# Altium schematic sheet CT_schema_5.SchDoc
size 577 x 363 mm
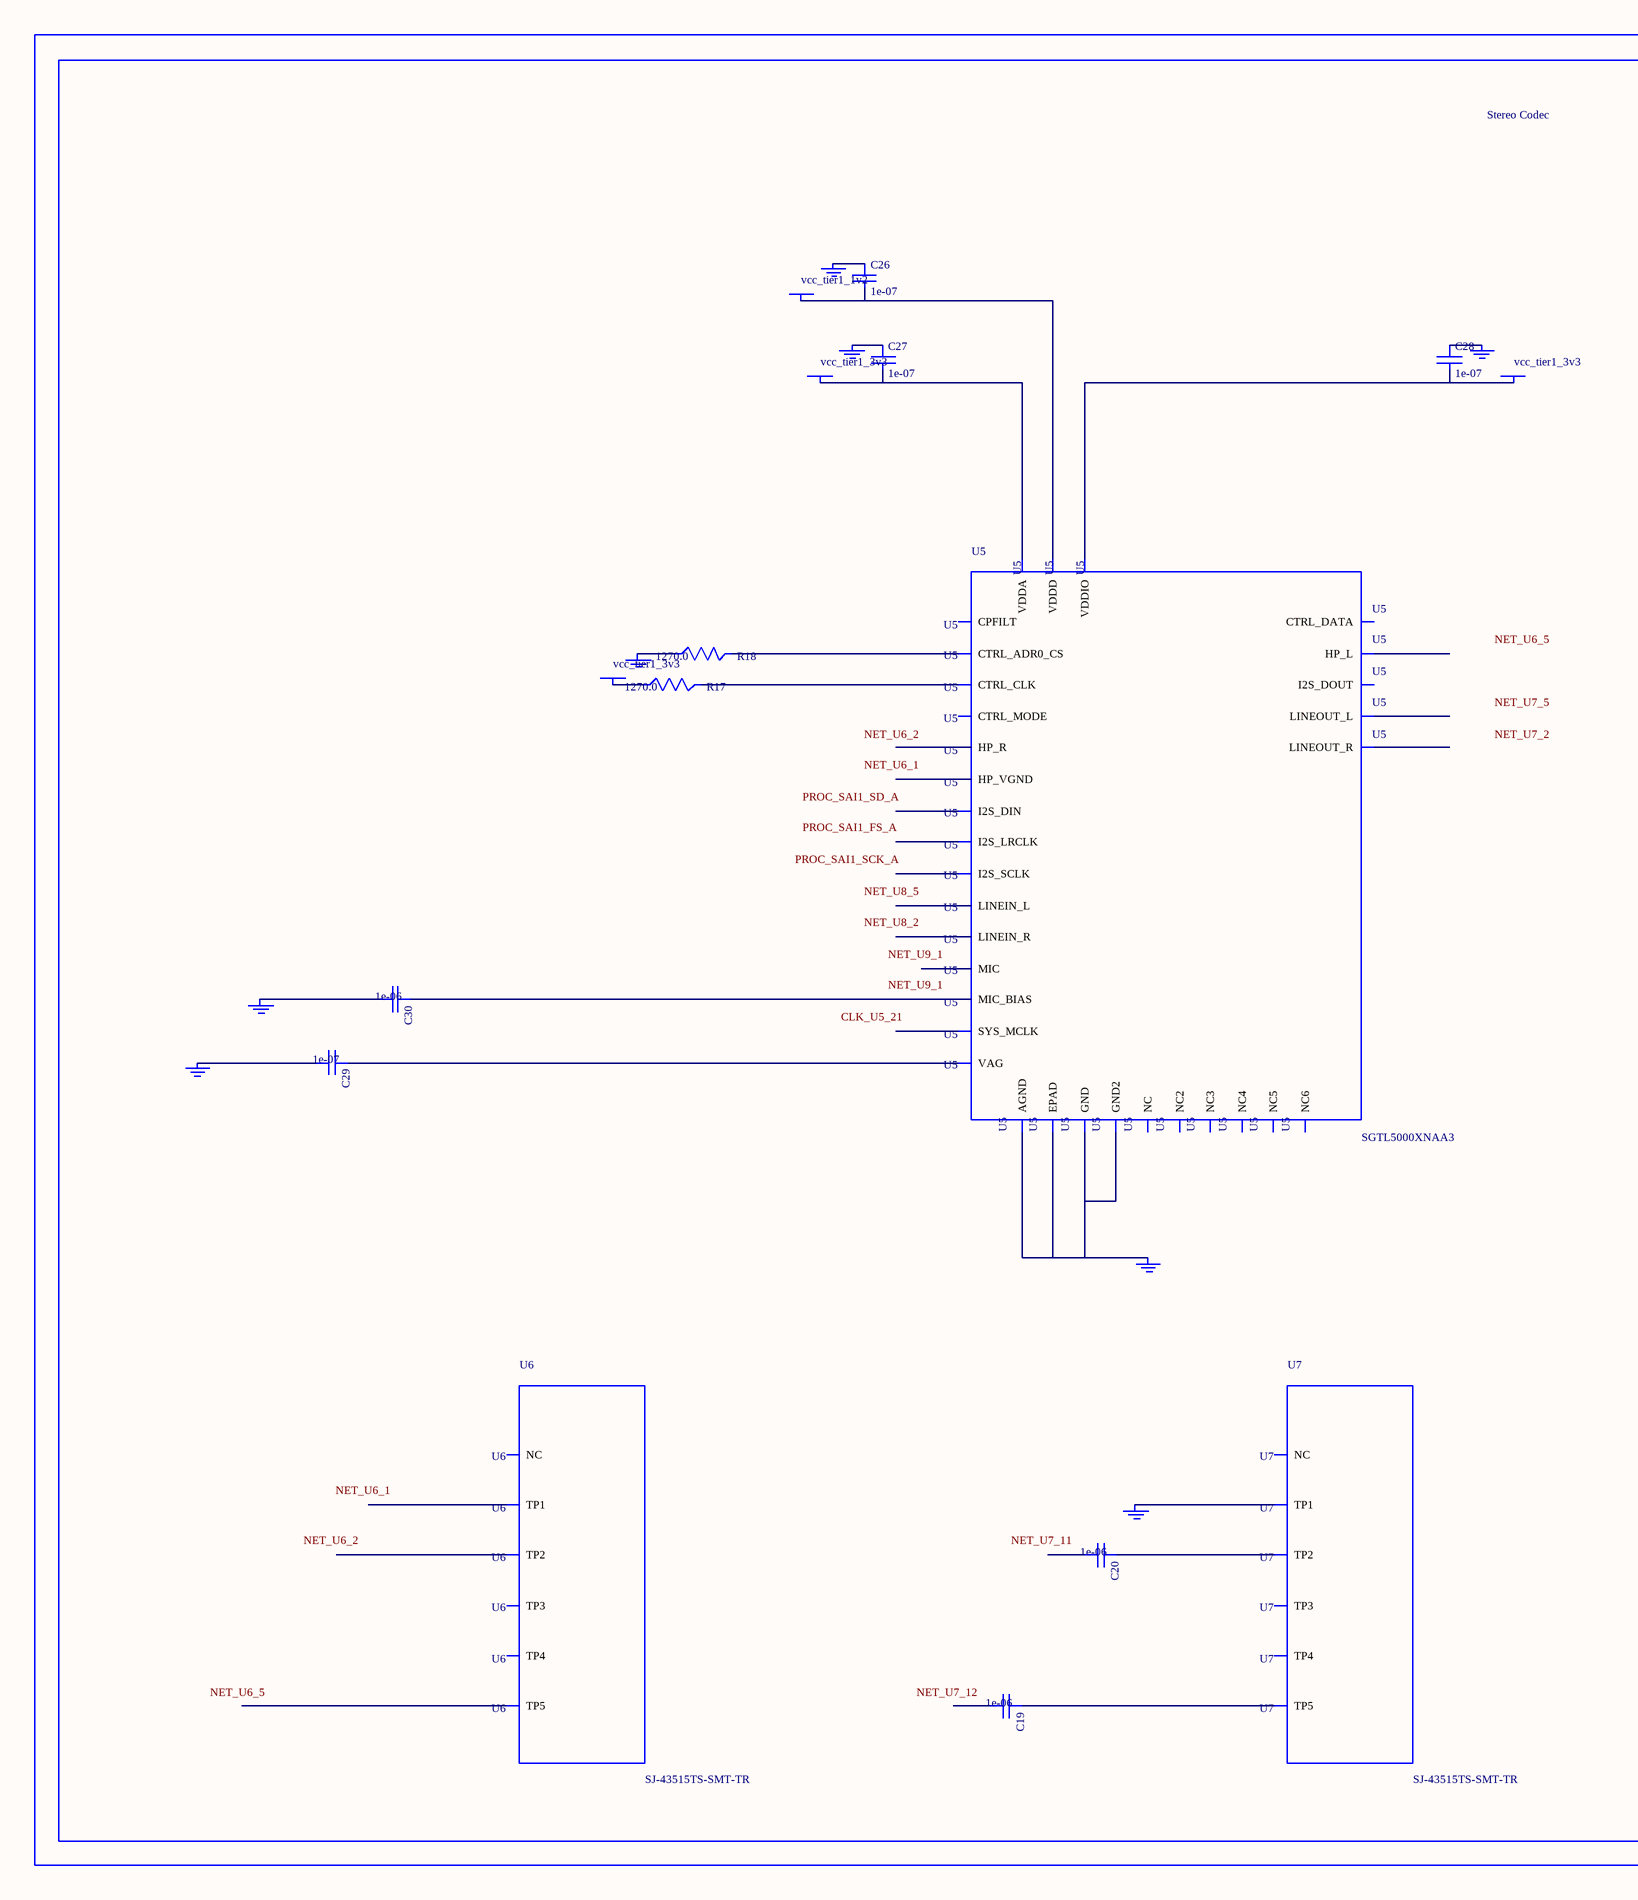
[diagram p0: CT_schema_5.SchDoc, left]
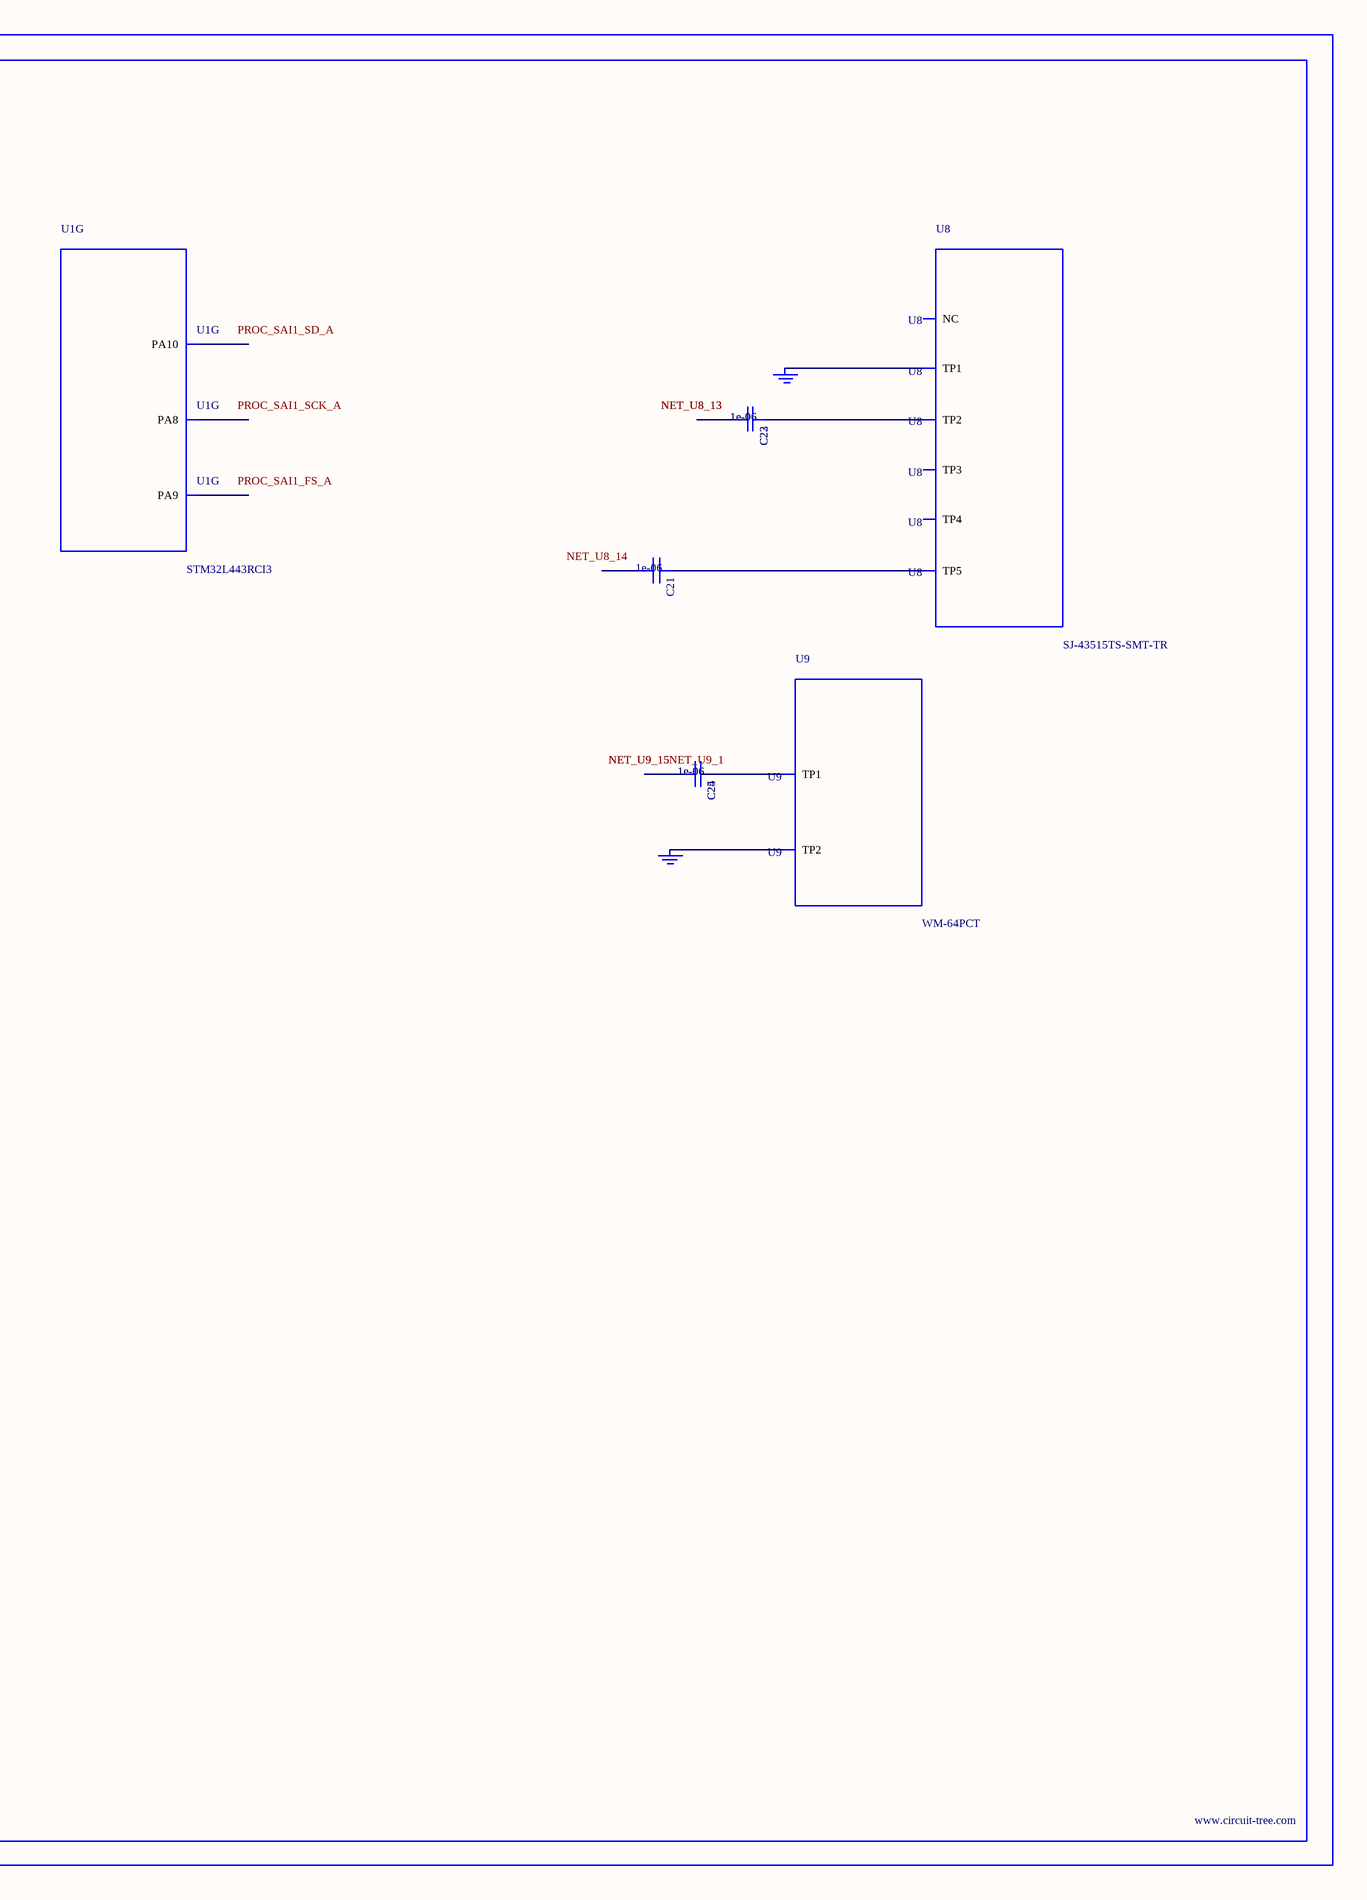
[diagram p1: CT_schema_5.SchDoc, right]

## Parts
BORDER4  (no value)
C19  1e-06  [C0603]
C20  1e-06  [C0603]
C21  1e-06  [C0603]
C22  1e-06  [C0603]
C23  1e-06  [C0603]
C24  1e-06  [C0603]
C25  1e-06  [C0603]
C26  1e-07  [C0402]
C27  1e-07  [C0402]
C28  1e-07  [C0402]
C29  1e-07  [C0402]
C30  1e-06  [C0603]
GND_INSTANCE_4_0  (no value)
GND_INSTANCE_4_1  (no value)
GND_INSTANCE_4_2  (no value)
GND_INSTANCE_4_3  (no value)
GND_INSTANCE_4_4  (no value)
GND_INSTANCE_4_5  (no value)
GND_INSTANCE_4_6  (no value)
GND_INSTANCE_4_7  (no value)
GND_INSTANCE_4_8  (no value)
GND_INSTANCE_4_9  (no value)
GND_INSTANCE_4_10  (no value)
POWER_INSTANCE_4_0  vcc_tier1_3v3
POWER_INSTANCE_4_1  vcc_tier1_3v3
POWER_INSTANCE_4_2  vcc_tier1_3v3
POWER_INSTANCE_4_3  vcc_tier1_1v2
R17  1270.0  [R0603]
R18  1270.0  [R0603]
U1  STM32L443RCI3  [UFBGA64]  (part G of 8)
U5  SGTL5000XNAA3  [QFN-32]
U6  SJ-43515TS-SMT-TR  [SJ-43515TS-SMT-TR]
U7  SJ-43515TS-SMT-TR  [SJ-43515TS-SMT-TR]
U8  SJ-43515TS-SMT-TR  [SJ-43515TS-SMT-TR]
U9  WM-64PCT  [WM-64PC]

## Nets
NetC19_1: C19.1 U7.5(TP5)
NetC20_1: C20.1 U7.2(TP2)
NetC21_1: C21.1 U8.5(TP5)
NetC22_1: C22.1 C23.1 U8.2(TP2)
NetC22_2: C22.2 C23.2
NetC24_1: C24.1 C25.1 U9.1(TP1)
NetC24_2: C24.2 C25.2
NetC26_1: C26.1 GND_INSTANCE_4_5.0(GND)
NetC26_2: C26.2 POWER_INSTANCE_4_3.0(PWR) U5.30(VDDD)
NetC27_1: C27.1 GND_INSTANCE_4_1.0(GND)
NetC27_2: C27.2 POWER_INSTANCE_4_0.0(PWR) U5.5(VDDA)
NetC28_1: C28.1 GND_INSTANCE_4_4.0(GND)
NetC28_2: C28.2 POWER_INSTANCE_4_1.0(PWR) U5.20(VDDIO)
NetC29_1: C29.1 U5.10(VAG)
NetC29_2: C29.2 GND_INSTANCE_4_2.0(GND)
NetC30_1: C30.1 U5.16(MIC_BIAS)
NetC30_2: C30.2 GND_INSTANCE_4_3.0(GND)
NetGND_INSTANCE_4_0_0: GND_INSTANCE_4_0.0(GND) U5.1(GND) U5.3(GND2) U5.7(AGND) U5.EXP(EPAD)
NetGND_INSTANCE_4_6_0: GND_INSTANCE_4_6.0(GND) R18.1
NetGND_INSTANCE_4_7_0: GND_INSTANCE_4_7.0(GND) U7.1(TP1)
NetGND_INSTANCE_4_8_0: GND_INSTANCE_4_8.0(GND) GND_INSTANCE_4_9.0(GND) U8.1(TP1)
NetGND_INSTANCE_4_10_0: GND_INSTANCE_4_10.0(GND) U9.2(TP2)
NetPOWER_INSTANCE_4_2_0: POWER_INSTANCE_4_2.0(PWR) R17.1
NetR17_2: R17.2 U5.29(CTRL_CLK)
NetR18_2: R18.2 U5.31(CTRL_ADR0_CS)

Not connected (* = marked no-connect by the designer): C19 2; C20 2; C21 2; U1 C6(PA10) C7(PA9) D7(PA8); U5 2(HP_R) 4(HP_VGND) 6(HP_L) 8(NC) 9(NC2) 11(LINEOUT_R) 12(LINEOUT_L) 13(LINEIN_R) 14(LINEIN_L) 15(MIC) 17(NC3) 18(CPFILT) 19(NC4) 21(SYS_MCLK) 22(NC5) 23(I2S_LRCLK) 24(I2S_SCLK) 25(I2S_DOUT) 26(I2S_DIN) 27(CTRL_DATA) 28(NC6) 32(CTRL_MODE); U6 1(TP1) 2(TP2) 3(TP3) 4(TP4) 5(TP5) 6(NC); U7 3(TP3) 4(TP4) 6(NC); U8 3(TP3) 4(TP4) 6(NC)

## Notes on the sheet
- Labels drawn without touching a wire or pin: CLK_U5_21, NET_U6_1, NET_U6_2, NET_U6_5, NET_U7_2, NET_U7_5, NET_U7_11, NET_U7_12, NET_U8_2, NET_U8_5, NET_U8_14, NET_U9_1, PROC_SAI1_FS_A, PROC_SAI1_SCK_A, PROC_SAI1_SD_A

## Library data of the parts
BORDER4 = BORDER_PAGE4
C19-C25 C30 = C0603C105K3RACTU
C26-C29 = C0402C104K3RACTU
GND_INSTANCE_4_0-GND_INSTANCE_4_10 = GND
POWER_INSTANCE_4_0-POWER_INSTANCE_4_3 = PWR
R17 R18 = RC0603FR-071K27L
